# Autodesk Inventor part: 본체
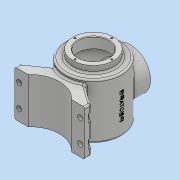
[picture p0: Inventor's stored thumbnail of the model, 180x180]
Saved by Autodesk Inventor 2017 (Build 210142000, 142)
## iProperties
Part Number: 본체
Material: 일반
Document SubType Name: Modeling
Designer: MRC
Density: 1 g/cm^3
Appearance: 기본값
Author: MRC
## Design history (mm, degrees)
sketch "스케치1"
  geometry: L1 (0, 62)-(0, -58); L2 (43, -41.887)-(43, 43); L3 (43, 43)-(27, 43); L4 (27, 43)-(27, 62); L5 (27, 62)-(36, 62); L6 (36, 62)-(36, 50); L7 (36, 50)-(50, 50); L8 (50, 50)-(50, -46.336); A1 r 106 centre (0, 55) between (0, -51) and (43, -41.887); A2 r 113 centre (0, 55) between (0, -58) and (50, -46.336); 1 further point
  constraints: 16 end point, 6 perpendicular, 4 point on circle, 3 point on line, 2 centre point, 2 vertical, 1 coincident, 1 horizontal alignment
  dimensions: "d0" = 120 distance of L1.start L1.end; "d1" = 62 distance of point (0, 0) L1.start; "d2" = 100 diameter of L8 L1; "d3" = 72 diameter of L6 L1; "d4" = 54 diameter of L4 L1; "d5" = 113 radius of A2; "d6" = 7 radial gap between concentric circles of A2 A1; "d7" = 86 diameter of L2 L1; "d8" = 19 distance of L3.end L4.end; "d9" = 108 distance from line of L7 L1.end
revolve "회전1" sketch "스케치1" stored, may be unused: angle "d10" = 90 deg
node "작업 평면1"
sketch "스케치2"
  geometry: C1 r 36 at (0, 0); 1 further point
  constraints: 1 centre point, 1 coincident
  dimensions: "d12" = 72 diameter of C1
extrude "돌출1" join sketch "스케치2" stored distance "d13" = 10; taper "d14" = 0 deg
sketch "스케치3"
  geometry: C1 r 27 at (0, 0); 1 further point
  constraints: 1 centre point, 1 coincident
  dimensions: "d15" = 54 diameter of C1
extrude "돌출2" cut sketch "스케치3" stored distance "d16" = 10; taper "d17" = 0 deg
node "작업 평면2"
sketch "스케치6"
  geometry: L1 (-26.694, -42.278)-(-62, -67); L2 (-62, -67)-(-62, -77); L3 (-62, -77)-(-38.5, -77); L4 (26.694, -42.278)-(62, -67); L5 (62, -67)-(62, -77); L6 (62, -77)-(38.5, -77); A1 r 50 centre (0, 0) between (-26.694, -42.278) and (26.694, -42.278) reference; A2 r 52.096 centre (0, -112.096) between (38.5, -77) and (-38.5, -77); 1 further point
  constraints: 12 end point, 4 point on circle, 2 equal length, 2 perpendicular, 2 vertical, 1 centre point, 1 collinear, 1 vertical alignment
  dimensions: "d41" = 77 distance of L6.end L3.end; "d42" = 124 distance between parallel lines of L2 L5; "d43" = 77 distance from line of L6 point (0, 0); "d44" = 17 distance edge to line of A2 L6; "d45" = 10 distance of L4.end L5.end; "d46" = 55 deg angle of L4 L5; "d47" = 55 deg angle of L2 L1
extrude "돌출3" join sketch "스케치6" stored distance "d48" = 80; taper "d49" = 0 deg
sketch "스케치7"
  geometry: L1 (23.5, -80)-(0, -80) reference; C1 r 4.5 at (8, -60); 1 further point
  constraints: 1 centre point
  dimensions: "d50" = 9 diameter of C1; "d51" = 54 horizontal distance of C1.centre point (62, -42); "d52" = 20 distance from line of L1 C1.centre
extrude "돌출4" cut sketch "스케치7" distance "d53" = 6; taper "d54" = 0 deg
sketch "스케치8"
  geometry: L1 (0, 7)-(-8, 7); L2 (-8, 7)-(-8, -7); L3 (-8, -7)-(0, -7); L4 (-8, -20)-(-8, 60) reference; C1 r 4.5 at (0, 0) reference; A1 r 7 centre (0, 0) between (0, -7) and (0, 7); 1 further point
  constraints: 6 end point, 2 perpendicular, 2 point on circle, 2 tangent, 1 centre point, 1 collinear, 1 concentric, 1 horizontal
  dimensions: "d55" = 14 diameter of A1
extrude "돌출5" cut sketch "스케치8" stored distance "d56" = 6; taper "d57" = 0 deg
node "작업 평면3"
sketch "스케치9"
  geometry: 2 further points
  constraints: 1 coincident, 1 other
feature "엠보싱1" sketch "스케치9" dims "d0" = 120, "d1" = 62, "d2" = 100, "d3" = 72, "d4" = 54, "d5" = 113, "d6" = 7, "d7" = 86, "d8" = 19, "d9" = 108, "d58" = 0.5, "d59" = 0
chamfer "모따기1" distance "d60" = 1; stored, may be unused: second distance "d61" = 2, angle "d62" = 45 deg
fillet "모깎기1" dims "d63" = 3
fillet "모깎기2" dims "d64" = 3
fillet "모깎기6" dims "d68" = 3
chamfer "모따기2" distance "d69" = 1; stored, may be unused: second distance "d70" = 2, angle "d71" = 45 deg
sketch "스케치10"
  geometry: 2 further points
  constraints: 1 vertical alignment
  dimensions: "d72" = 32.5 distance of point (0, 0) point (0, 32.5)
hole "구멍3" sketch "스케치10" at (0, 32.5) diameter "d73" = 3.242; stored, may be unused: countersink angle "d77" = 90 deg, drill point angle "d79" = 118 deg; dims "d74" = 8, "d75" = 4, "d76" = 2, "d78" = 10
sketch "스케치11"
  geometry: 2 further points
  constraints: 1 horizontal alignment
  dimensions: "d83" = 31 distance of point (0, 0) point (-31, 0)
hole "구멍4" sketch "스케치11" at (-31, 0) diameter "d84" = 3.242; stored, may be unused: countersink angle "d88" = 90 deg, drill point angle "d90" = 118 deg; dims "d85" = 8, "d86" = 4, "d87" = 2, "d89" = 10
node "솔리드1"
mirror "미러1"
mirror "미러2"
pattern_circular "원형 패턴3" dims angle "d81" = 360 deg
pattern_circular "원형 패턴5" dims angle "d95" = 360 deg
other parameters: "d11" = 65
